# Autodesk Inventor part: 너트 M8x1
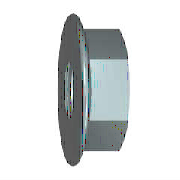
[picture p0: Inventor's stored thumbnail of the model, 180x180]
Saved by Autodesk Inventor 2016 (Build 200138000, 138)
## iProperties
Created: 2015-12
Part Number: 너트 M8x1
Material: 스테인리스강
Description: 플랜지붙이 6각 너트 - 일반 스레드
Document SubType Name: Modeling
Standard: ISO 4161
Designer: mdu
Standard Revision: 2판 1999-03-15
Standards Organization: ISO
Language: ko-KR
Size Designation: M8
Categories: <MemberInstance><Categories><Category DisplayName="조임쇠" InternalName="e4da775c-781d-43d5-af7c-5136215cf5a6" Mnemonic="FSTN"><Category DisplayName="너트" InternalN
Density: 8.08 g/cm^3
Appearance: 기본값
Mass: 9.03298 g
Surface Area: 8.90186 cm^2
Volume: 1.11794 cm^3
Author: mdu
IsCustomPart: 1
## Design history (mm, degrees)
sketch "스케치1"
  geometry: L1 (-1.844, 0)-(9.641, 0) reference; L2 (3.107, 6.5)-(2.288, 8.257); L3 (3.107, 6.5)-(8, 6.5); L4 (8, 6.5)-(8, 0); L5 (3.107, 6.5)-(3.107, 0); L6 (0, -1.835)-(0, 11.01) reference; A1 r 1.2 centre (1.2, 7.75) between (2.288, 8.257) and (0, 7.75); 1 further point
  constraints: 8 end point, 3 point on line, 2 perpendicular, 2 point on circle, 2 tangent, 1 centre point, 1 parallel
  dimensions: "d2" = 13 diameter of L3 L1 (= SW); "d4" = 17.9 dimension on A1 L1 (= LADI); "d5" = 1.2 radius of A1 (= PHH); "d15" = 8 distance between parallel lines of L4 L6 (= KOH); "d16" = 25 deg angle of L6 L2 (= KEWI)
revolve "링" sketch "스케치1" stored, may be unused: angle "d8" = 90 deg
sketch "스케치2"
  geometry: L1 (-6.5, -3.753)-(-6.5, 3.753); L2 (-6.5, 3.753)-(0, 7.506); L3 (0, 7.506)-(6.5, 3.753); L4 (6.5, 3.753)-(6.5, -3.753); L5 (6.5, -3.753)-(0, -7.506); L6 (0, -7.506)-(-6.5, -3.753); C1 r 4.9 at (0, 0); C2 r 7.75 at (0, 0) reference; 1 further point
  constraints: 12 end point, 1 centre point, 1 coincident, 1 vertical, 11 other
  dimensions: "d6" = 15.01111 distance of L5.end L2.end (= 1.1547 x SW)
extrude "본체" join sketch "스케치2" distance "d7" = 8 (= KOH); taper "d9" = 0 deg
sketch "스케치3"
  geometry: L1 (2.638, 7.506)-(8, 7.506) reference; L2 (8, 3.753)-(8, 7.506) reference; L3 (0, -7.75)-(0, 7.75) reference; L4 (-1.6, 0)-(9.6, 0) reference; L5 (7.419, 7.506)-(8, 6.5)
  constraints: 2 end point, 2 point on line
  dimensions: "d10" = 30 deg angle of L2 L5 (= ANG1); "d11" = 13 diameter of L5.end L4 (= SW0)
revolve "모따기1" sketch "스케치3" stored, may be unused: angle "d24" = 90 deg
sketch "스케치4"
  geometry: C1 r 7.75 at (0, 0) reference; 1 further point
  constraints: 1 coincident
hole "스레드" sketch "스케치4" at (0, 0) diameter "d25" = 6.647; stored, may be unused: countersink angle "d29" = 82 deg, drill point angle "d31" = 118 deg; dims "d26" = 6, "d27" = 4, "d28" = 2, "d30" = 8
workaxis "Work Axis1"
workplane "Work Plane1"
body "Solid1"
chamfer "모따기2" distance "d12" = 0.67658 (= -0.5 x GD1 + 0.5 x NND); stored, may be unused: angle "d13" = 30 deg, second distance "d46" = 0.67658 (= -0.5 x GD1 + 0.5 x NND)
chamfer "모따기3" distance "d51" = 0.67658 (= -0.5 x GD1 + 0.5 x NND); stored, may be unused: second distance "d52" = 2, angle "d53" = 45 deg
other parameters: "ANG1" = 30 deg [user parameter; used in 1 equation term], "KEWI" = 25 deg [user parameter; used in 1 equation term], "NND" = 8 [user parameter; used in 4 equation terms], "LADI" = 17.9 [user parameter; used in 2 equation terms], "SW" = 13 [user parameter; used in 3 equation terms], "PHH" = 1.2 [user parameter; used in 3 equation terms], "KOH" = 8 (= NND) [user parameter; used in 2 equation terms], "SW0" = 13 [user parameter; used in 1 equation term], "GD1" = 6.64684 (computed from THREADDIA, PTC, TOA) [user parameter; used in 3 equation terms], "d1" = 17.9 (= LADI), "d3" = 1.2 (= PHH), "d45" = 0, "d47" = 0, "d49" = 0, "d54" = 0, "GUL" = 0.67658 (= 0.541266 x PTC) [user parameter], "TPU" = 8 (computed from PTC) [user parameter], "RR" = 1.2 (= PHH) [user parameter], "THREADDIA" = 8 [user parameter; used in 1 equation term], "TOA" = 30 deg [user parameter; used in 1 equation term], "PTC" = 1.25 [user parameter; used in 4 equation terms], "GAL" = 0.67658 (= 0.541266 x PTC) [user parameter], "E0" = 15.015 (= 1.155 x SW) [user parameter]
